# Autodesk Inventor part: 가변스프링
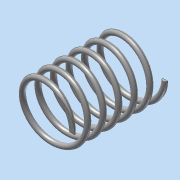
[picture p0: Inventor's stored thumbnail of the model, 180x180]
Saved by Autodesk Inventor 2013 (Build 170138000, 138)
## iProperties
Created: 2018-06
Part Number: 가변스프링
Material: 강철, 연강
Document SubType Name: Modeling
Designer: Administrator
Mass: -1.23315 g
Surface Area: 106.42 cm^2
Volume: -0.156889 cm^3
Density: 7.86 g/cm^3
Author: Administrator
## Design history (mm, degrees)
sketch "스케치1"
  geometry: L1 (0, 0)-(0, 73.25); L2 (0, 0)-(22.5, 0); L3 (0, 73.25)-(22.5, 73.25); C1 r 2 at (22.5, 0)
  constraints: 6 end point, 1 centre point, 1 parallel, 1 perpendicular, 1 vertical
  dimensions: "d0" = 4 diameter of C1; "d1" = 73.25 distance of L1.start L1.end (derived); "d2" = 22.5 distance of L1.start L2.end; "d3" = 45 diameter of L3.end L1
feature "코일1" sketch "스케치1" pitch "d4" = 10; turns "d6" = 6; dims "d5" = 73.25 (= d1), "d7" = 0, angle "d8" = 90 deg, angle "d9" = 90 deg, "d10" = 0, "d11" = 0
sketch "스케치2"
  geometry: L1 (73.25, 27.5)-(0, 27.5); L2 (0, 27.5)-(0, -27.5); L3 (0, -27.5)-(73.25, -27.5); L4 (73.25, -27.5)-(73.25, 27.5); 2 further points
  constraints: 8 end point, 2 parallel, 1 coincident, 1 horizontal, 1 midpoint, 1 perpendicular
  dimensions: "d12" = 73.25 distance of L1.start L1.end (derived); "d14" = 55 distance of L3.end L1.start
extrude "돌출1" sketch "스케치2" stored distance "d15" = 60; taper "d16" = 0 deg
node "솔리드1"
